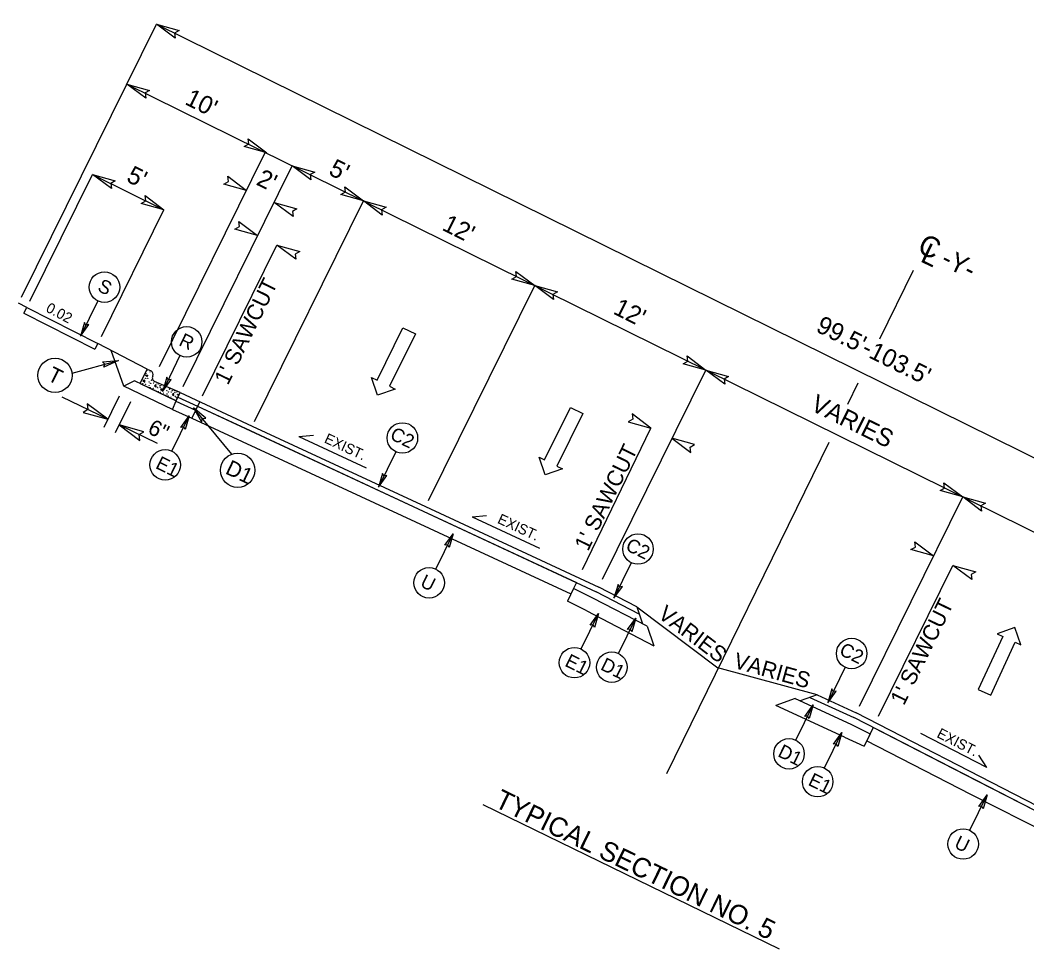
# Model space of a CAD drawing. Extents: x 1518247 to 1523638, y 635234 to 639927.
# Drawn here: x 1522079 to 1522712, y 635551 to 636134 of the extents above; entities that cross this region are included whole.
import ezdxf

# ---------------------------------------------------------------- set-up
doc = ezdxf.new("R2010")
doc.units = 0
for name, color, linetype in [('DTM TIN Hull White', 7, 'Continuous'), ('Prop Dimension', 7, 'Continuous'), ('Prop Dimension Text', 7, 'Continuous'), ('Prop Lane Arrow CELL', 7, 'Continuous'), ('Prop Shade Light', 7, 'Continuous'), ('Sheet Typical CELL', 7, 'Continuous'), ('Typical Berm CELL', 7, 'Continuous'), ('Typical Berm Information CELL', 7, 'Continuous'), ('Typical Curb CELL', 7, 'Continuous'), ('Typical Hinge Slope Arterial CELL', 7, 'Continuous'), ('Typical Hinge Slope Interstate CELL', 7, 'Continuous'), ('Typical ID Circle CELL', 7, 'Continuous'), ('Typical Pavement Slope CELL', 7, 'Continuous'), ('Typical Pavement Slope Information CELL', 7, 'Continuous'), ('Typical Shoulder Slope CELL', 7, 'Continuous'), ('Typical Text Centerline CELL', 7, 'Continuous'), ('Typical Text ID Circle CELL', 7, 'Continuous'), ('Typical Text Label CELL', 7, 'Continuous')]:
    doc.layers.add(name, color=color, linetype=linetype)

# ---------------------------------------------------------------- blocks, each defined once
blk = doc.blocks.new('TERMINATOR')
at = {"layer": 'Prop Shade Light'}
blk.add_lwpolyline([(-0.469, 0.081), (0, 0), (-0.471, -0.083), (-0.411, 0)], close=True, dxfattribs=at)

msp = doc.modelspace()

# ---------------------------------------------------------------- linework, layer by layer
at = {"layer": 'DTM TIN Hull White'}
for p, q in [((1522190.83, 635891.95), (1522429.06, 635781.11)), ((1522187.27, 635884.38), (1522425.47, 635774.03)), ((1522681, 635656.43), (1522615.37, 635690.17)), ((1522676.71, 635648.08), (1522611.18, 635681.77)), ((1522849.5, 635569.87), (1522681, 635656.43)), ((1522845.72, 635562.41), (1522676.71, 635648.08))]:
    msp.add_line(p, q, dxfattribs=at)
at = {"layer": 'Prop Dimension'}
for p, q in [((1522080.42, 635960.52), (1522165.11, 636131.96)), ((1522165.11, 636131.96), (1523054.02, 635692.85)), ((1522146.52, 636094.32), (1523035.43, 635655.21)), ((1522166.94, 635916.77), (1522233.44, 636051.38)), ((1522181.91, 635904.41), (1522250.38, 636043.02)), ((1522085.66, 635957.94), (1522124.95, 636037.49)), ((1522124.95, 636037.49), (1522169.78, 636015.34)), ((1522226.72, 635882.27), (1522295.19, 636020.88)), ((1522130.49, 635935.79), (1522169.78, 636015.34)), ((1522194.04, 635898.42), (1522240.82, 635993.13)), ((1522336.02, 635832.71), (1522402.73, 635967.75)), ((1522445.4, 635783.3), (1522510.28, 635914.63)), ((1522134.55, 635883.69), (1522105.91, 635897.67)), ((1522141.61, 635898.15), (1522132.08, 635878.63)), ((1522148.78, 635894.65), (1522139.25, 635875.13)), ((1522165.72, 635868.47), (1522141.72, 635880.19)), ((1522432.81, 635789.4), (1522475.8, 635878.2)), ((1522606.8, 635703.58), (1522671.68, 635834.9)), ((1522618.73, 635697.16), (1522665.51, 635791.87))]:
    msp.add_line(p, q, dxfattribs=at)
at = {"layer": 'Prop Lane Arrow CELL'}
for p, q in [((1522303.71, 635908.25), (1522320, 635941.21)), ((1522327.76, 635937.37), (1522311.48, 635904.42)), ((1522320, 635941.21), (1522327.76, 635937.37)), ((1522304.05, 635898.86), (1522300.18, 635910)), ((1522300.18, 635910), (1522303.71, 635908.25)), ((1522311.48, 635904.42), (1522315.01, 635902.67)), ((1522315.01, 635902.67), (1522304.05, 635898.86)), ((1522408.98, 635858.16), (1522425.26, 635891.12)), ((1522425.26, 635891.12), (1522433.03, 635887.28)), ((1522433.03, 635887.28), (1522416.75, 635854.32)), ((1522409.32, 635848.77), (1522405.45, 635859.9)), ((1522405.45, 635859.9), (1522408.98, 635858.16)), ((1522416.75, 635854.32), (1522420.28, 635852.58)), ((1522420.28, 635852.58), (1522409.32, 635848.77)), ((1522704.36, 635752.94), (1522693.26, 635748.98)), ((1522708.26, 635742.01), (1522704.36, 635752.94)), ((1522696.83, 635747.32), (1522681.35, 635713.98)), ((1522693.26, 635748.98), (1522696.83, 635747.32)), ((1522689.21, 635710.33), (1522704.69, 635743.67)), ((1522704.69, 635743.67), (1522708.26, 635742.01)), ((1522681.35, 635713.98), (1522689.21, 635710.33))]:
    msp.add_line(p, q, dxfattribs=at)
at = {"layer": 'Prop Shade Light'}
for points in [[(1522119.87, 635944.51), (1522117.35, 635935.86), (1522122.68, 635943.19), (1522120.77, 635942.87)], [(1522131.15, 635919.74), (1522141.24, 635920.62), (1522131.98, 635916.35), (1522132.76, 635918.39)], [(1522171.55, 635910.11), (1522169.03, 635901.46), (1522174.36, 635908.79), (1522172.45, 635908.47)], [(1522180.42, 635878.62), (1522185.7, 635885.92), (1522183.19, 635877.21), (1522182.27, 635878.92)], [(1522196.09, 635884.38), (1522188.39, 635890.96), (1522193.44, 635882.11), (1522193.99, 635884.22)], [(1522307.07, 635849.75), (1522304.55, 635841.1), (1522309.88, 635848.43), (1522307.97, 635848.1)], [(1522346.22, 635804.56), (1522351.49, 635811.86), (1522348.98, 635803.15), (1522348.07, 635804.86)], [(1522455.09, 635779.99), (1522452.56, 635771.34), (1522457.9, 635778.67), (1522455.98, 635778.34)], [(1522437.54, 635754.37), (1522442.82, 635761.66), (1522440.31, 635752.95), (1522439.39, 635754.67)], [(1522460.99, 635751.57), (1522466.27, 635758.87), (1522463.76, 635750.16), (1522462.85, 635751.87)], [(1522589.35, 635714.32), (1522586.83, 635705.67), (1522592.16, 635713), (1522590.25, 635712.67)], [(1522572.36, 635697.11), (1522577.64, 635704.41), (1522575.12, 635695.7), (1522574.21, 635697.41)], [(1522590.37, 635679.62), (1522595.65, 635686.92), (1522593.14, 635678.21), (1522592.22, 635679.92)], [(1522681.71, 635640.47), (1522686.99, 635647.77), (1522684.48, 635639.06), (1522683.57, 635640.77)]]:
    msp.add_lwpolyline(points, close=True, dxfattribs=at)
at = {"layer": 'Sheet Typical CELL'}
for p, q in [((1522081.88, 635950.41), (1522083.7, 635953.97)), ((1522081.88, 635950.41), (1522126.43, 635927.69)), ((1522083.7, 635953.97), (1522128.25, 635931.25)), ((1522128.25, 635931.25), (1522126.43, 635927.69))]:
    msp.add_line(p, q, dxfattribs=at)
at = {"layer": 'Typical Berm CELL'}
for p, q in [((1522083.7, 635953.97), (1522078.51, 635956.65)), ((1522159.35, 635915.23), (1522128.25, 635931.25))]:
    msp.add_line(p, q, dxfattribs=at)
at = {"layer": 'Typical Curb CELL'}
for p, q in [((1522154.96, 635906.25), (1522159.35, 635915.23)), ((1522159.05, 635910.66), (1522158.02, 635911.67)), ((1522158.02, 635911.67), (1522159.6, 635911.4)), ((1522159.6, 635911.4), (1522159.05, 635910.66)), ((1522159.35, 635915.23), (1522161.69, 635914.08)), ((1522162.75, 635910.78), (1522162.79, 635910.88)), ((1522154.96, 635906.25), (1522177.42, 635895.26)), ((1522157.75, 635908.25), (1522156.5, 635908.03)), ((1522156.5, 635908.03), (1522157.81, 635906.95)), ((1522157.81, 635906.95), (1522157.75, 635908.25)), ((1522164.66, 635905.5), (1522163.85, 635904.63)), ((1522163.85, 635904.63), (1522164.9, 635904.05)), ((1522179.98, 635900.5), (1522163.94, 635907.54)), ((1522164.9, 635904.05), (1522164.66, 635905.5)), ((1522168.97, 635902.77), (1522167.72, 635902.55)), ((1522167.72, 635902.55), (1522169.03, 635901.46)), ((1522169.03, 635901.46), (1522168.97, 635902.77)), ((1522175.88, 635900.02), (1522175.07, 635899.15)), ((1522175.07, 635899.15), (1522176.13, 635898.56)), ((1522176.13, 635898.56), (1522175.88, 635900.02)), ((1522177.42, 635895.26), (1522179.98, 635900.5))]:
    msp.add_line(p, q, dxfattribs=at)
for centre in [(1522158.65, 635912.31), (1522158.99, 635914.18), (1522161.09, 635913.54), (1522156.46, 635906.02), (1522158.18, 635905.63), (1522158.32, 635909.43), (1522159.49, 635904.29), (1522159.62, 635909.36), (1522160.49, 635907.1), (1522160.51, 635905.06), (1522161.16, 635903.79), (1522161.49, 635906.3), (1522161.99, 635907.96), (1522162.06, 635908.49), (1522163.2, 635906.41), (1522163.9, 635907.2), (1522165.48, 635906), (1522165.73, 635903.65), (1522166.54, 635905.96), (1522167.15, 635904.74), (1522167.53, 635903.85), (1522167.8, 635904.8), (1522169.54, 635903.95), (1522170.84, 635903.87), (1522163.1, 635903.09), (1522164.24, 635901.78), (1522166.23, 635901.06), (1522166.39, 635902.82), (1522167.69, 635900.54), (1522169.4, 635900.14), (1522170.71, 635898.8), (1522171.71, 635901.62), (1522171.73, 635899.57), (1522172.38, 635898.3), (1522172.71, 635900.81), (1522173.21, 635902.47), (1522173.28, 635903), (1522174.32, 635897.61), (1522174.42, 635900.93), (1522175.12, 635901.72), (1522176.7, 635900.51), (1522176.73, 635901.63), (1522176.95, 635898.17), (1522177.61, 635897.33), (1522177.94, 635900.85), (1522178.37, 635899.25), (1522178.75, 635898.37), (1522179.02, 635899.31), (1522175.46, 635896.29), (1522177.45, 635895.57)]:
    msp.add_circle(centre, 0.0802, dxfattribs=at)
for centre, start, end in [((1522160.64, 635911.93), 333.93772, 63.93772), ((1522164.9, 635909.73), 153.93772, 246.32218)]:
    msp.add_arc(centre, 2.4, start, end, dxfattribs=at)
at = {"layer": 'Typical Hinge Slope Interstate CELL'}
for p, q in [((1522144.66, 635904.53), (1522136.67, 635926.91)), ((1522151.22, 635907.97), (1522144.66, 635904.53)), ((1522175.18, 635889.92), (1522144.66, 635904.53)), ((1522177.42, 635895.26), (1522151.22, 635907.97)), ((1522175.18, 635889.92), (1522177.42, 635895.26)), ((1522192.26, 635894.81), (1522187.27, 635884.38)), ((1522429.06, 635781.11), (1522427.14, 635777.36)), ((1522615.37, 635690.17), (1522612.93, 635684.84))]:
    msp.add_line(p, q, dxfattribs=at)
for points in [[(1522466.85, 635765.98), (1522517.81, 635727.51)], [(1522580.24, 635710.53), (1522517.81, 635727.51)]]:
    msp.add_lwpolyline(points, dxfattribs=at)
at = {"layer": 'Typical ID Circle CELL'}
for p, q in [((1522128.22, 635958.13), (1522117.35, 635935.86)), ((1522179.9, 635923.73), (1522169.03, 635901.46)), ((1522112.2, 635912.72), (1522141.26, 635920.59)), ((1522174.8, 635863.67), (1522185.7, 635885.92)), ((1522212.56, 635861.88), (1522188.39, 635890.96)), ((1522315.42, 635863.36), (1522304.55, 635841.1)), ((1522340.59, 635789.61), (1522351.49, 635811.86)), ((1522463.43, 635793.6), (1522452.56, 635771.34)), ((1522431.92, 635739.42), (1522442.82, 635761.66)), ((1522455.37, 635736.62), (1522466.27, 635758.87)), ((1522597.7, 635727.94), (1522586.83, 635705.67)), ((1522566.73, 635682.16), (1522577.64, 635704.41)), ((1522584.75, 635664.67), (1522595.65, 635686.92)), ((1522676.09, 635625.52), (1522686.99, 635647.77))]:
    msp.add_line(p, q, dxfattribs=at)
for centre, radius in [((1522132.42, 635966.74), 9.59), ((1522184.1, 635932.34), 9.59), ((1522101.37, 635911.27), 10.78), ((1522319.62, 635871.98), 9.59), ((1522170.58, 635855.06), 9.59), ((1522216.17, 635851.72), 10.78), ((1522467.64, 635802.22), 9.59), ((1522336.38, 635781), 9.59), ((1522601.9, 635736.55), 9.59), ((1522427.7, 635730.81), 9.59), ((1522451.16, 635728.01), 9.59), ((1522562.52, 635673.55), 9.59), ((1522580.53, 635656.06), 9.59), ((1522671.88, 635616.91), 9.59)]:
    msp.add_circle(centre, radius, dxfattribs=at)
at = {"layer": 'Typical Pavement Slope CELL'}
for p, q in [((1522179.98, 635900.5), (1522225.32, 635879.44)), ((1522190.83, 635891.95), (1522223.93, 635876.58)), ((1522225.32, 635879.44), (1522334.14, 635828.89)), ((1522223.93, 635876.58), (1522332.74, 635826.03)), ((1522334.14, 635828.89), (1522442.95, 635778.34)), ((1522332.74, 635826.03), (1522441.41, 635775.36)), ((1522709.97, 635641.53), (1522603.27, 635696.39)), ((1522711.37, 635644.39), (1522604.67, 635699.25)), ((1522818.08, 635589.54), (1522711.37, 635644.39)), ((1522816.68, 635586.68), (1522709.97, 635641.53))]:
    msp.add_line(p, q, dxfattribs=at)
at = {"layer": 'Typical Pavement Slope Information CELL'}
for p, q in [((1522254.62, 635872.93), (1522263.73, 635873.74)), ((1522254.62, 635872.93), (1522296.9, 635853.29)), ((1522363.44, 635822.38), (1522372.55, 635823.19)), ((1522363.44, 635822.38), (1522405.71, 635802.74)), ((1522686.75, 635664.99), (1522645.29, 635686.31)), ((1522686.75, 635664.99), (1522681.79, 635672.68))]:
    msp.add_line(p, q, dxfattribs=at)
at = {"layer": 'Typical Shoulder Slope CELL'}
for p, q in [((1522178.58, 635897.64), (1522190.83, 635891.95)), ((1522177.33, 635895.08), (1522189.58, 635889.39)), ((1522175.18, 635889.92), (1522187.27, 635884.38)), ((1522427.14, 635777.36), (1522423.3, 635769.49)), ((1522439.35, 635771.37), (1522427.14, 635777.36)), ((1522466.85, 635765.98), (1522442.95, 635778.34)), ((1522473.49, 635753.71), (1522439.35, 635771.37)), ((1522468.42, 635761.38), (1522441.41, 635775.36)), ((1522435.43, 635763.3), (1522423.3, 635769.49)), ((1522466.85, 635765.98), (1522470.51, 635755.26)), ((1522435.43, 635763.3), (1522477.67, 635741.45)), ((1522473.49, 635753.71), (1522477.67, 635741.45)), ((1522566.47, 635708.24), (1522554.23, 635704.01)), ((1522566.47, 635708.24), (1522601.38, 635692.13)), ((1522580.24, 635710.53), (1522569.52, 635706.83)), ((1522575.64, 635708.94), (1522603.27, 635696.39)), ((1522580.24, 635710.53), (1522604.67, 635699.25)), ((1522597.41, 635684.08), (1522554.23, 635704.01)), ((1522601.38, 635692.13), (1522613.6, 635686.17)), ((1522597.41, 635684.08), (1522609.74, 635678.31)), ((1522613.6, 635686.17), (1522609.74, 635678.31))]:
    msp.add_line(p, q, dxfattribs=at)
at = {"layer": 'Typical Text Centerline CELL'}
for p, q in [((1522619.58, 635934.27), (1522640.68, 635977.33)), ((1522599.51, 635893.31), (1522606.05, 635906.66)), ((1522485.82, 635661.27), (1522587.78, 635869.36))]:
    msp.add_line(p, q, dxfattribs=at)
at = {"layer": 'Typical Text Label CELL'}
msp.add_line((1522370.18, 635641.66), (1522556.39, 635551.05), dxfattribs=at)

# ---------------------------------------------------------------- block references
at = {"layer": 'Prop Dimension'}
for p, xscale, yscale, rotation in [((1522165.11, 636131.96), 30.9388560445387, 33.305184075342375, 153.71146049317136), ((1522146.52, 636094.32), 30.9388560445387, 33.305184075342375, 153.71146049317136), ((1522234.47, 636051.1), 30.9388560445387, 33.305184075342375, -26.28853950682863), ((1522250.38, 636043.02), 30.9388560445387, 33.305184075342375, 153.71146049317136), ((1522124.95, 636037.49), 30.9388560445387, 33.305184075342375, 153.71146049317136), ((1522221.76, 636027.52), 30.9388560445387, 33.305184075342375, -26.28853950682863), ((1522169.78, 636015.34), 30.9388560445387, 33.305184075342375, -26.28853950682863), ((1522295.19, 636020.88), 30.9388560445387, 33.305184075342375, -26.28853950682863), ((1522239.11, 636019.97), 30.9388560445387, 33.305184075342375, 153.71146049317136), ((1522295.19, 636020.88), 30.9388560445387, 33.305184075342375, 153.71146049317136), ((1522228.63, 635999.09), 30.9388560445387, 33.305184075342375, -26.28853950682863), ((1522240.82, 635993.13), 30.9388560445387, 33.305184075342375, 153.71146049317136), ((1522402.73, 635967.75), 30.9388560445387, 33.305184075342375, -26.28853950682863), ((1522402.73, 635967.75), 30.9388560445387, 33.305184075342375, 153.71146049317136), ((1522510.28, 635914.63), 30.9388560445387, 33.305184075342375, -26.28853950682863), ((1522510.28, 635914.63), 30.9388560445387, 33.305184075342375, 153.71146049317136), ((1522134.55, 635883.69), 33.82820784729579, -36.41552511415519, -26.020730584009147), ((1522475.8, 635878.2), 30.938856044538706, -33.30518407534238, -25.836011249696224), ((1522141.72, 635880.19), 33.82820784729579, -36.41552511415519, 153.97926941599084), ((1522488.98, 635871.76), 30.938856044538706, -33.30518407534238, 154.1639887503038), ((1522671.68, 635834.9), 30.9388560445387, 33.305184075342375, -26.28853950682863), ((1522671.68, 635834.9), 30.9388560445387, 33.305184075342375, 153.71146049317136), ((1522653.32, 635797.84), 30.9388560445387, 33.305184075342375, -26.28853950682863), ((1522665.51, 635791.87), 30.9388560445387, 33.305184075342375, 153.71146049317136)]:
    msp.add_blockref('TERMINATOR', p, dxfattribs=dict(at, xscale=xscale, yscale=yscale, rotation=rotation))

# ---------------------------------------------------------------- texts
for s, height, rotation, p in [("10'", 11.189, 333.71146, (1522182.31, 636081.9)), ("5'", 11.189, 333.71146, (1522145.56, 636033.44)), ("5'", 11.189, 333.71146, (1522272.64, 636037.7)), ("2'", 11.189, 333.71146, (1522227.18, 636031.37)), ("12'", 11.189, 333.71146, (1522343.92, 636002.86)), ("1' SAWCUT", 10, 63.93772, (1522210, 635904.68)), ("12'", 11.189, 333.71146, (1522451.41, 635950.28)), ("99.5'-103.5'", 11.1894, 333.71146, (1522578.75, 635939.17)), ('VARIES', 11.189, 333.71146, (1522575.37, 635889.72)), ('6"', 9.969, 333.97927, (1522158.91, 635875.24)), ("1' SAWCUT", 10, 63.93772, (1522436.23, 635800.39)), ("1' SAWCUT", 10, 63.93772, (1522634.69, 635703.43))]:
    msp.add_text(s, height=height, rotation=rotation, dxfattribs=at).set_placement(p)
at = {"layer": 'Prop Dimension Text'}
for s, height, rotation, p in [('-Y-', 11.962, 333.97927, (1522657.17, 635980.88)), ('TYPICAL SECTION NO. 5', 12.2298, 334.0511, (1522376.77, 635640.67))]:
    msp.add_text(s, height=height, rotation=rotation, dxfattribs=at).set_placement(p)
at = {"layer": 'Typical Berm Information CELL'}
msp.add_text('0.02', height=6.491, rotation=331.75967, dxfattribs=at).set_placement((1522095.11, 635951.68))
at = {"layer": 'Typical Hinge Slope Arterial CELL'}
for rotation, p in [(322.90061, (1522479.53, 635759.65)), (344.29392, (1522527.09, 635727.74))]:
    msp.add_text('VARIES', height=9.969, rotation=rotation, dxfattribs=at).set_placement(p)
at = {"layer": 'Typical Pavement Slope Information CELL'}
for rotation, p in [(335.08347, (1522270.02, 635869.32)), (335.08347, (1522378.83, 635818.78)), (332.79198, (1522654.88, 635684.29))]:
    msp.add_text('EXIST.', height=6.476, rotation=rotation, dxfattribs=at).set_placement(p)
at = {"layer": 'Typical Text Centerline CELL'}
for s, height, rotation, p in [('C', 13.08, 333.89618, (1522642.4, 635989.11)), ('L', 13.09, 333.84308, (1522644.34, 635983.18))]:
    msp.add_text(s, height=height, rotation=rotation, dxfattribs=at).set_placement(p)
at = {"layer": 'Typical Text ID Circle CELL'}
for s, height, rotation, p in [('S', 8.58, 333.97927, (1522127.49, 635964.64)), ('R', 8.58, 333.97927, (1522178.62, 635930.51)), ('T', 9.65, 333.61889, (1522095.96, 635908.53)), ('C2', 8.581, 333.97927, (1522311.19, 635871.58)), ('E1', 8.581, 333.89618, (1522163.97, 635853.25)), ('D1', 9.65, 334.53754, (1522207.78, 635849.86)), ('C2', 8.581, 333.97927, (1522459.21, 635801.82)), ('U', 8.58, 333.89618, (1522330.22, 635778.97)), ('C2', 8.581, 333.97927, (1522593.47, 635736.16)), ('E1', 8.581, 333.89618, (1522421.09, 635729)), ('D1', 8.581, 333.89618, (1522443.5, 635726.72)), ('D1', 8.581, 333.89618, (1522554.87, 635672.25)), ('E1', 8.581, 333.89618, (1522573.93, 635654.25)), ('U', 8.58, 333.89618, (1522665.72, 635614.88))]:
    msp.add_text(s, height=height, rotation=rotation, dxfattribs=at).set_placement(p)

doc.saveas('drawing.dxf')
